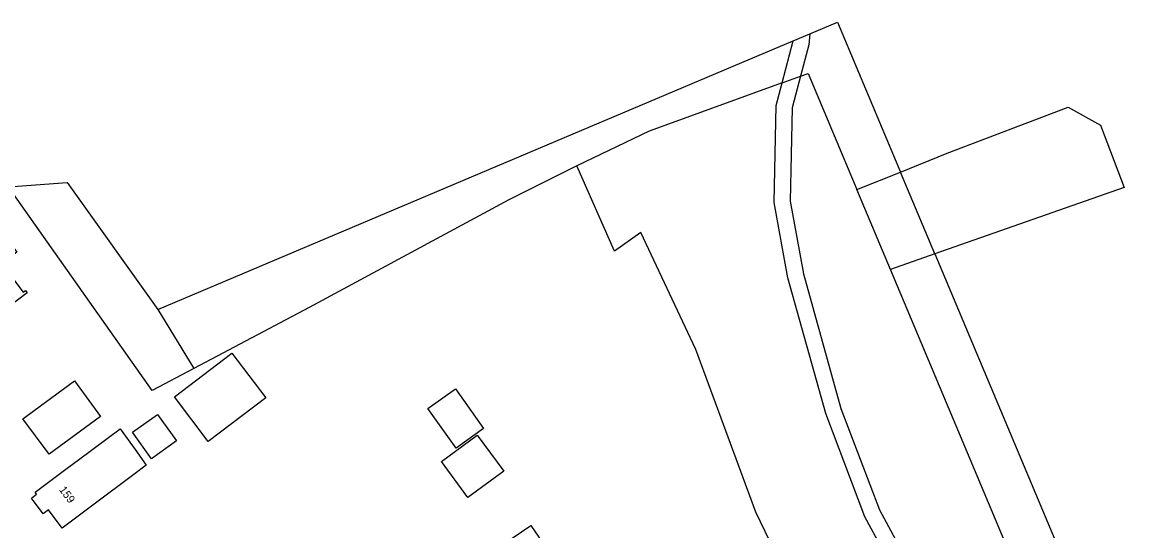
# Model space of a CAD drawing. Extents: x 164494 to 166241, y 382475 to 384494.
# Drawn here: x 165007.7 to 165146.3, y 383241.1 to 383304.7 of the extents above; entities that cross this region are included whole.
import ezdxf

# ---------------------------------------------------------------- set-up
doc = ezdxf.new("R2010")
doc.units = 0
for name, color, linetype in [('IMGEO_Grasland_overig', 7, 'Continuous'), ('IMGEO_Hek', 7, 'Continuous'), ('IMGEO_Loofbos', 7, 'Continuous'), ('IMGEO_Pand', 7, 'Continuous'), ('IMGEO_Pand_nummerreeks', 7, 'Continuous'), ('IMGEO_Pand_vergunning_verleend', 7, 'Continuous')]:
    doc.layers.add(name, color=color, linetype=linetype)

msp = doc.modelspace()

# ---------------------------------------------------------------- linework, layer by layer
at = {"layer": 'IMGEO_Grasland_overig'}
for points in [[(165104, 383302.35), (165106.09, 383303.23)], [(165102.63, 383297.11), (165104.92, 383297.95)], [(165005.99, 383284.12), (165013.31, 383284.65), (165024.64, 383268.79)], [(165029.15, 383261.42), (165023.92, 383258.65), (165006.08, 383283.99), (165005.99, 383284.12)]]:
    msp.add_lwpolyline(points, dxfattribs=at)
at = {"layer": 'IMGEO_Hek'}
msp.add_lwpolyline([(165076.97, 383286.72), (165068.46, 383282.49), (165043.52, 383269.03)], dxfattribs=at)
at = {"layer": 'IMGEO_Loofbos'}
for points in [[(165106.09, 383303.23), (165109.54, 383304.69), (165117.4, 383285.96)], [(165106.09, 383303.23), (165105.95, 383301.87), (165104.92, 383297.95)], [(165024.64, 383268.79), (165098.65, 383300.09), (165104, 383302.35)], [(165102.63, 383297.11), (165104, 383302.35)], [(165104.92, 383297.95), (165103.87, 383293.98), (165103.61, 383282.31), (165105.28, 383273.24), (165109.96, 383256.39), (165114.79, 383243.72), (165121, 383232.23), (165125.46, 383226.56), (165136.35, 383213.72), (165137.17, 383212.86)], [(165104.92, 383297.95), (165105.87, 383298.29), (165111.96, 383283.77)], [(165102.63, 383297.11), (165086.01, 383291.05), (165076.97, 383286.72)], [(165136.11, 383211.07), (165134.91, 383212.33), (165123.91, 383225.29), (165119.32, 383231.12), (165112.96, 383242.88), (165108.06, 383255.76), (165103.34, 383272.75), (165101.61, 383282.15), (165101.88, 383294.26), (165102.63, 383297.11)], [(165117.4, 383285.96), (165123.23, 383288.3), (165138.36, 383294.08), (165142.4, 383291.83), (165145.36, 383284.04), (165121.69, 383275.73)], [(165076.97, 383286.72), (165068.46, 383282.49), (165043.52, 383269.03), (165029.15, 383261.42)], [(165120.91, 383186.94), (165121.54, 383188.74), (165121.94, 383191.31), (165121.81, 383193.49), (165121.35, 383196.33), (165115.94, 383209), (165099.32, 383243.43), (165091.83, 383263.76), (165084.98, 383278.41), (165081.69, 383276.07), (165076.97, 383286.72)], [(165111.96, 383283.77), (165117.4, 383285.96)], [(165121.69, 383275.73), (165117.4, 383285.96)], [(165116.15, 383273.78), (165111.96, 383283.77)], [(165121.69, 383275.73), (165116.15, 383273.78)], [(165121.69, 383275.73), (165146.3, 383217.1), (165141.11, 383208.76)], [(165137.17, 383212.86), (165140.91, 383219.27), (165130.47, 383239.66), (165116.15, 383273.78)], [(165024.64, 383268.79), (165029.15, 383261.42)]]:
    msp.add_lwpolyline(points, dxfattribs=at)
at = {"layer": 'IMGEO_Pand'}
for points in [[(165002.76, 383266.71), (165001.69, 383268.12), (164995.36, 383263.35), (164991.51, 383268.45), (165005.07, 383278.57), (165007.02, 383275.95), (165005.1, 383274.51), (165007.81, 383270.93), (165008.09, 383271.14), (165008.29, 383270.88), (165002.76, 383266.71)], [(165030.91, 383252.26), (165026.71, 383257.88), (165033.89, 383263.31), (165038.11, 383257.73), (165030.91, 383252.26)], [(165058.36, 383256.39), (165061.81, 383258.85), (165065.33, 383253.91), (165061.89, 383251.45), (165058.36, 383256.39)], [(165023.86, 383250.12), (165021.48, 383253.44), (165024.59, 383255.66), (165026.97, 383252.35), (165023.86, 383250.12)], [(165016.69, 383244.44), (165012.69, 383241.44), (165010.98, 383243.72), (165010.33, 383243.23), (165008.84, 383245.21), (165009.49, 383245.7), (165009.3, 383245.95), (165013.3, 383248.95), (165014.72, 383250), (165019.93, 383253.86), (165021.79, 383251.27), (165023.19, 383249.33), (165021.63, 383248.16), (165016.69, 383244.44)], [(165060.05, 383249.77), (165064.54, 383253.08), (165067.86, 383248.59), (165063.37, 383245.28), (165060.05, 383249.77)], [(165067.6, 383239.34), (165071.21, 383241.8), (165073.76, 383238.06), (165070.14, 383235.6), (165067.6, 383239.34)]]:
    msp.add_lwpolyline(points, dxfattribs=at)
at = {"layer": 'IMGEO_Pand_vergunning_verleend'}
msp.add_lwpolyline([(165014.24, 383259.86), (165017.49, 383255.42), (165011.05, 383250.69), (165007.79, 383255.12), (165014.24, 383259.86)], dxfattribs=at)

# ---------------------------------------------------------------- texts
at = {"layer": 'IMGEO_Pand_nummerreeks'}
msp.add_text('159', height=1, rotation=306.9269, dxfattribs=at).set_placement((165012.24, 383246.24))

doc.saveas('drawing.dxf')
